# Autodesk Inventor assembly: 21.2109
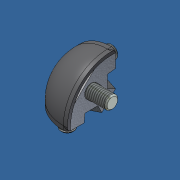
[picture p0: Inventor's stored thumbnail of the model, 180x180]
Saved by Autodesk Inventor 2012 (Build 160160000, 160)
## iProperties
Created: 2012-08
Part Number: 21.2109
Document SubType Name: Assembly
Designer: Administrator
Description: ANGLE 30 R 90 CAP
Author: Administrator
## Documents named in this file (4)
- C:\Andys Backup Data\ANDY'S INVENTOR\INVENTOR LIBRARIES\PARTS LIBRARY\30 SERIES\21.2109 ANGLE 30 R 90.iam
- C:\Andys Backup Data\ANDY'S INVENTOR\INVENTOR LIBRARIES\PARTS LIBRARY\30 SERIES\SUBCOMPONENTS\ANGLE 30 R 90 BRACKET.ipt
- C:\Andys Backup Data\ANDY'S INVENTOR\INVENTOR LIBRARIES\PARTS LIBRARY\30 SERIES\SUBCOMPONENTS\ANGLE 30 R 90 CAP.ipt
- C:\Andys Backup Data\ANDY'S INVENTOR\INVENTOR LIBRARIES\PARTS LIBRARY\FASTENING ELEMENTS\SCREWS CAP\21.1200 M8X16.ipt
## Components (5 placed, 3 different names)
1. ANGLE 30 R 90 BRACKET:1 — Mate:1, Angle:1, Mate:2, Insert:1, Insert:2, Insert:3
2. ANGLE 30 R 90 CAP:1 — Mate:1, Angle:1, Mate:2
3. 21.1200 M8 x 16:1 — Insert:2
4. 21.1200 M8 x 16:2 — Insert:1
5. 21.1200 M8 x 16:3 — Insert:3
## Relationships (6: Insert 3, Mate 2, Angle 1)
- Mate:1: ANGLE 30 R 90 BRACKET:1 ↔ ANGLE 30 R 90 CAP:1
- Angle:1: ANGLE 30 R 90 BRACKET:1 ↔ ANGLE 30 R 90 CAP:1
- Mate:2: ANGLE 30 R 90 BRACKET:1 ↔ ANGLE 30 R 90 CAP:1
- Insert:1: ANGLE 30 R 90 BRACKET:1 ↔ 21.1200 M8 x 16:2
- Insert:2: ANGLE 30 R 90 BRACKET:1 ↔ 21.1200 M8 x 16:1
- Insert:3: ANGLE 30 R 90 BRACKET:1 ↔ 21.1200 M8 x 16:3
